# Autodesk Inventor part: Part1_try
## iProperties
Created: 2009-03
Part Number: Part1_try
Document SubType Name: Modeling
Designer: Sham
Density: 1 g/cm^3
Author: Sham
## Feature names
1. Extrusion3
